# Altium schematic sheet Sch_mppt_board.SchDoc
size A4; Organization: Altium Limited; Address1: L3, 12a Rodborough Rd; Address2: Frenchs Forest; Address3: NSW; Address4: Australia 2086
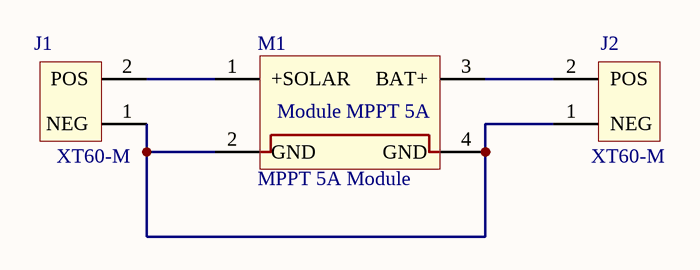
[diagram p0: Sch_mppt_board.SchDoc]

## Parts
J1  XT60-M  [XT60-M]
J2  XT60-M  [XT60-M]
M1  MPPT 5A Module  [MODULE MPPT 5A BQ24650]

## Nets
NetJ1_1: J1.1(NEG) J2.1(NEG) M1.2(GND) M1.4(GND)
NetJ1_2: J1.2(POS) M1.1(+SOLAR)
NetJ2_2: J2.2(POS) M1.3(BAT+)

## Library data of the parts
J1 J2 = XT60-M: MF: AMASS
M1 = Module BQ24650 MPPT 5A: Module Solar Charge MPPT 5A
